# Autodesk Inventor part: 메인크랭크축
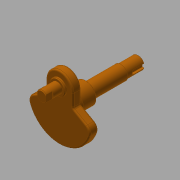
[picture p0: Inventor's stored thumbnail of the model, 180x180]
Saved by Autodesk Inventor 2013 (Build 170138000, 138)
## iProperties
Created: 2016-11
Part Number: 메인크랭크축
Material: 강철, 탄소
Document SubType Name: Modeling
Designer: mduedu
Density: 1 g/cm^3
Author: mduedu
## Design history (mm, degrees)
sketch "스케치1" dims "d8" = 65
  geometry: L1 (-19, 26.368)-(-19, 8.368); L2 (-19, 8.368)-(-44.545, -6.381); L3 (0, 26.368)-(0, -45); L4 (19, 26.368)-(19, 8.368); L5 (19, 8.368)-(44.545, -6.381); C1 r 10 at (0, 0); C2 r 17.5 at (0, 0); A1 r 45 centre (0, 0) between (-44.545, -6.381) and (0, -45); A2 r 19 centre (0, 26.368) between (0, 45.368) and (-19, 26.368); A3 r 19 centre (0, 26.368) between (19, 26.368) and (0, 45.368); A4 r 45 centre (0, 0) between (0, -45) and (44.545, -6.381); 2 further points
  constraints: 10 end point, 8 point on circle, 6 centre point, 4 coincident, 3 symmetric about line, 2 point on line, 1 parallel, 1 tangent, 1 vertical, 1 vertical alignment, 5 other
  dimensions: "d1" = 20 diameter of C1; "d2" = 35 diameter of C2; "d4" = 18 distance of L1.start L1.end; "d5" = 120 deg angle of L2 L1; "d6" = 45 radius of A1; "d9" = 19 radius of A2
extrude "돌출1" new body sketch "스케치1" distance "d10" = 12; taper "d11" = 0 deg
extrude "돌출2" join sketch "스케치1" distance "d12" = 5; taper "d13" = 0 deg
extrude "돌출3" join sketch "스케치1" distance "d14" = 100; taper "d15" = 0 deg
sketch "스케치2"
  geometry: C1 r 7.5 at (0, 26.368); C2 r 11 at (0, 26.368); A1 r 19 centre (0, 26.368) between (19, 26.368) and (-19, 26.368) reference; 1 further point
  constraints: 2 centre point, 2 coincident
  dimensions: "d16" = 15 diameter of C1; "d17" = 22 diameter of C2
extrude "돌출4" join sketch "스케치2" distance "d18" = 3; taper "d19" = 0 deg
extrude "돌출5" join sketch "스케치2" distance "d20" = 25; taper "d21" = 0 deg
node "작업 평면1"
sketch "스케치3"
  geometry: L1 (-5.75, -4.815)-(5.75, -4.815); L2 (5.75, -4.815)-(5.75, 4.815); L3 (5.75, 4.815)-(-5.75, 4.815); L4 (-5.75, 4.815)-(-5.75, -4.815); L5 (-5.75, -4.815)-(5.75, 4.815); L6 (5.75, -4.815)-(-5.75, 4.815); A1 r 7.5 centre (0, 0) between (-5.75, 4.815) and (-5.75, -4.815); A2 r 7.5 centre (0, 0) between (5.75, -4.815) and (5.75, 4.815); 2 further points
  constraints: 12 end point, 4 point on circle, 2 centre point, 2 midpoint, 2 parallel, 1 coincident, 1 horizontal, 1 perpendicular, 2 other
  dimensions: "d23" = 11.5 distance between parallel lines of L2 L4
extrude "돌출6" cut sketch "스케치3" stored distance "d25" = 25; taper "d26" = 0 deg
fillet "모깎기1" dims "d27" = 3, "d29" = 10
fillet "모깎기2" dims "d28" = 2
sketch "스케치4"
  geometry: C1 r 15 at (0, 0); 1 further point
  constraints: 1 centre point, 1 coincident
  dimensions: "d30" = 30 diameter of C1
extrude "돌출7" join sketch "스케치4" distance "d31" = 21; taper "d32" = 0 deg
sketch "스케치5"
  geometry: C1 r 10 at (0, 0) reference; C2 r 9 at (0, 0); 1 further point
  constraints: 1 centre point
  dimensions: "d33" = 1 radial gap between concentric circles of C1 C2
extrude "돌출8" cut sketch "스케치5" distance "d34" = 25; taper "d35" = 0 deg
node "작업 평면2"
sketch "스케치6"
  geometry: L1 (-9, 0)-(9, 0) reference; L2 (-3, 0)-(3, 0); L3 (3, 0)-(3, 15); L4 (-3, 15)-(-3, 0); A1 r 3 centre (0, 15) between (3, 15) and (-3, 15); 1 further point
  constraints: 6 end point, 2 point on circle, 2 tangent, 1 centre point, 1 horizontal, 1 parallel, 1 perpendicular, 1 point on line, 1 vertical alignment
  dimensions: "d36" = 18 dimension on A1 L1; "d37" = 6 distance between parallel lines of L3 L4
extrude "돌출9" cut sketch "스케치6" distance "d38" = 3.5; taper "d39" = 0 deg
chamfer "모따기1" distance "d40" = 1; stored, may be unused: second distance "d41" = 2, angle "d42" = 45 deg
chamfer "모따기2" distance "d43" = 1; stored, may be unused: second distance "d44" = 2, angle "d45" = 45 deg
node "솔리드1"
node "투영된 루프1"
other parameters: "d3" = 38, "d22" = 13
